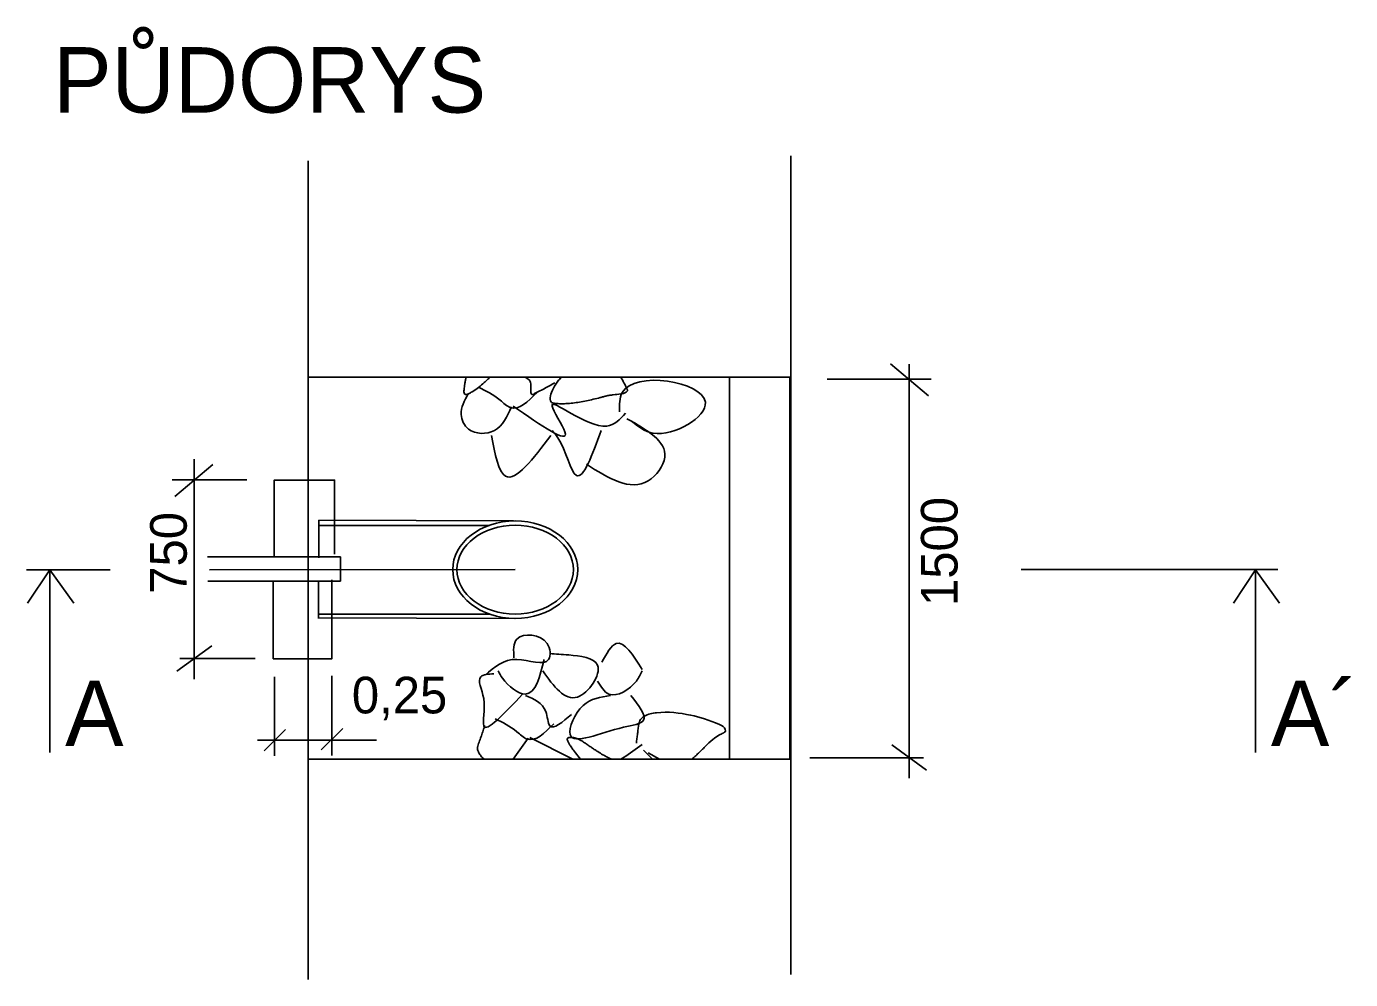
# Model space of a CAD drawing. Extents: x -463101.2 to -463058.2, y -1105044.4 to -1105011.4.
# Drawn here: x -463094.07 to -463083.23, y -1105030.57 to -1105022.77 of the extents above; entities that cross this region are included whole.
import ezdxf

# ---------------------------------------------------------------- set-up
doc = ezdxf.new("R2010")
doc.units = 0
doc.layers.add('Vrstva 14', color=7, linetype='Continuous')

msp = doc.modelspace()

# ---------------------------------------------------------------- linework, layer by layer
at = {"layer": 'Vrstva 14'}
for p, q in [((-463091.76794376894, -1105023.87000803), (-463091.76794376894, -1105030.5724223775)), ((-463087.8165389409, -1105023.8280037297), (-463087.8165389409, -1105030.5304180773)), ((-463086.99958763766, -1105025.531277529), (-463086.68764795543, -1105025.7934618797)), ((-463086.84766558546, -1105025.53473319), (-463086.84766558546, -1105028.9249225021)), ((-463088.31817793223, -1105025.6400270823), (-463091.7672940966, -1105025.6400270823)), ((-463087.8189958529, -1105025.6400270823), (-463088.31817793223, -1105025.6400270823)), ((-463088.31817793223, -1105025.6400270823), (-463088.31817793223, -1105028.7677961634)), ((-463087.82523562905, -1105028.7677961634), (-463087.82523562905, -1105025.6433654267)), ((-463087.51911575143, -1105025.6567217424), (-463086.6675204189, -1105025.6567217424)), ((-463092.54826919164, -1105026.3559565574), (-463092.86020887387, -1105026.6181409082)), ((-463092.70019124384, -1105026.3112801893), (-463092.70019124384, -1105028.1137976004)), ((-463092.27081989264, -1105026.4814007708), (-463092.8803364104, -1105026.4814007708)), ((-463091.68192638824, -1105027.1210487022), (-463091.68192638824, -1105026.811372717)), ((-463091.68192638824, -1105026.811372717), (-463090.08590284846, -1105026.8173622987)), ((-463091.6818170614, -1105026.854244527), (-463090.2832931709, -1105026.854244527)), ((-463091.5030528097, -1105027.112724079), (-463092.5921017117, -1105027.112724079)), ((-463091.5030528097, -1105027.310850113), (-463091.5030528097, -1105027.112724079)), ((-463094.07454247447, -1105027.218025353), (-463093.39045514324, -1105027.217837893)), ((-463093.88432615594, -1105027.2198520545), (-463093.6869389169, -1105027.4923547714)), ((-463092.57463033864, -1105027.2176143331), (-463090.07254473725, -1105027.2169286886)), ((-463085.93030603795, -1105027.2157935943), (-463083.82688213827, -1105027.2152171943)), ((-463084.0108773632, -1105027.2198520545), (-463083.81349012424, -1105027.4923547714)), ((-463092.58907011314, -1105027.310850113), (-463091.5030528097, -1105027.310850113)), ((-463091.6844222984, -1105027.3104338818), (-463091.6844222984, -1105027.6159563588)), ((-463091.68480347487, -1105027.612150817), (-463090.0753138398, -1105027.6165200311)), ((-463091.6844222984, -1105027.5801516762), (-463090.2864260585, -1105027.5801516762)), ((-463092.55799873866, -1105027.839473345), (-463092.8432007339, -1105028.0487452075)), ((-463092.2022732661, -1105027.945707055), (-463092.81898827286, -1105027.945707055)), ((-463092.0442134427, -1105028.0938394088), (-463092.0442134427, -1105028.7407540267)), ((-463091.5736301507, -1105028.0867051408), (-463091.5736301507, -1105028.7383759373)), ((-463092.129133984, -1105028.699839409), (-463091.953133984, -1105028.5258394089)), ((-463091.66055069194, -1105028.692705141), (-463091.48455069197, -1105028.5187051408)), ((-463092.18254953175, -1105028.6138394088), (-463091.2082134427, -1105028.6138394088)), ((-463089.9668118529, -1105028.597650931), (-463090.08959707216, -1105028.7677961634)), ((-463089.95281185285, -1105028.591650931), (-463089.60072510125, -1105028.7677961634)), ((-463086.98985809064, -1105028.6504018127), (-463086.7046560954, -1105028.8596736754)), ((-463088.31817793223, -1105028.7677961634), (-463091.7672940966, -1105028.7677961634)), ((-463089.0208118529, -1105028.695650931), (-463088.9487704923, -1105028.7677961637)), ((-463088.8898941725, -1105028.7677961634), (-463088.9828118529, -1105028.715650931)), ((-463088.31817793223, -1105028.7677961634), (-463087.82523562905, -1105028.7677961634)), ((-463087.66052840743, -1105028.756635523), (-463086.72886855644, -1105028.756635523))]:
    msp.add_line(p, q, dxfattribs=at)
for points in [[(-463092.0463878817, -1105027.1189083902), (-463092.0463878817, -1105026.4837396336), (-463091.55136565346, -1105026.4837396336), (-463091.55136565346, -1105027.0897722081)], [(-463093.88432615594, -1105028.714180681), (-463093.88432615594, -1105027.2198520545), (-463094.06566395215, -1105027.4923547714)], [(-463084.0108773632, -1105028.714180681), (-463084.0108773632, -1105027.2198520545), (-463084.1922151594, -1105027.4923547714)], [(-463091.57323458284, -1105027.3008608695), (-463091.57323458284, -1105027.9459002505), (-463092.0543510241, -1105027.9459002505), (-463092.0543510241, -1105027.3122774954)]]:
    msp.add_lwpolyline(points, dxfattribs=at)
for major_axis, ratio in [((0.5118952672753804, 0), 0.7792053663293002), ((0.47700487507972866, 0), 0.7630554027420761)]:
    msp.add_ellipse((-463090.07254473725, -1105027.2169286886), major_axis=major_axis, ratio=ratio, dxfattribs=at)
for points in [[(-463089.21736382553, -1105025.9239442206), (-463089.1973638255, -1105025.7679442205), (-463088.5153638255, -1105025.8459442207), (-463088.9433638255, -1105026.0999442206), (-463089.11936382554, -1105026.0019442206)], [(-463090.27786681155, -1105025.6400270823), (-463090.30171401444, -1105025.6625953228), (-463090.3255342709, -1105025.6844926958), (-463090.3730563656, -1105025.7248573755), (-463090.4203579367, -1105025.7582861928), (-463090.4439025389, -1105025.7715137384), (-463090.45564418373, -1105025.77710076), (-463090.46150682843, -1105025.7796182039), (-463090.464436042, -1105025.7808054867), (-463090.4659001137, -1105025.7813809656), (-463090.46663201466, -1105025.781664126), (-463090.46736382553, -1105025.7819442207), (-463090.4709831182, -1105025.783105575), (-463090.4742658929, -1105025.7837156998), (-463090.4798698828, -1105025.7833583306), (-463090.4875675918, -1105025.7768656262), (-463090.49160965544, -1105025.745028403), (-463090.4856333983, -1105025.6961698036), (-463090.48080820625, -1105025.6684003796), (-463090.4757822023, -1105025.6400270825)], [(-463089.8933638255, -1105025.7659442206), (-463090.1133638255, -1105025.8899442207), (-463090.19536382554, -1105025.8299442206), (-463090.3733638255, -1105025.7239442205)], [(-463089.7473638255, -1105025.6879442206), (-463089.8363742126, -1105025.7354741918), (-463089.8809168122, -1105025.75896262), (-463089.90315791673, -1105025.7705318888), (-463089.91426597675, -1105025.7762595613), (-463089.9253638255, -1105025.7819442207), (-463089.92854551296, -1105025.7832982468), (-463089.9313403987, -1105025.7839325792), (-463089.9358697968, -1105025.7831999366), (-463089.94138732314, -1105025.7748338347), (-463089.94385909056, -1105025.7393336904), (-463089.9455832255, -1105025.695638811), (-463089.95016621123, -1105025.6770292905), (-463089.9593638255, -1105025.6639442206), (-463089.9898438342, -1105025.6400270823)], [(-463089.2076965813, -1105025.6400270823), (-463089.15736382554, -1105025.7359442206), (-463089.155282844, -1105025.7406332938), (-463089.15411682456, -1105025.7449794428), (-463089.15435126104, -1105025.7527059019), (-463089.1638371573, -1105025.7647360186), (-463089.2088860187, -1105025.77862944), (-463089.2696737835, -1105025.785680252), (-463089.29883330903, -1105025.789157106), (-463089.3118556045, -1105025.7913239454), (-463089.3178212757, -1105025.7925695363), (-463089.3233638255, -1105025.7939442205), (-463089.35023387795, -1105025.8011824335), (-463089.37756314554, -1105025.8083756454), (-463089.43324913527, -1105025.8222669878), (-463089.5462796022, -1105025.845548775), (-463089.6568521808, -1105025.8580282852), (-463089.70946581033, -1105025.858416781), (-463089.73479804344, -1105025.856833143), (-463089.74718221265, -1105025.8555574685), (-463089.75329902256, -1105025.8547937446), (-463089.7593638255, -1105025.8539442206), (-463089.7650533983, -1105025.8526644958), (-463089.77002024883, -1105025.8506431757), (-463089.7778731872, -1105025.8445328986), (-463089.7858678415, -1105025.825141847), (-463089.7759068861, -1105025.7664781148), (-463089.7406686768, -1105025.6980681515), (-463089.71706676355, -1105025.6664943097), (-463089.70438193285, -1105025.6524652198), (-463089.6913409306, -1105025.6400270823)], [(-463090.10336382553, -1105025.8839442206), (-463090.2433638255, -1105026.0779442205), (-463090.4553638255, -1105026.0659442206), (-463090.5153638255, -1105025.9479442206), (-463090.4573638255, -1105025.7779442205)], [(-463090.0893638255, -1105025.8779442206), (-463089.6653638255, -1105026.0899442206), (-463089.77136382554, -1105025.8779442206), (-463089.3233638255, -1105026.0419442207), (-463089.1693638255, -1105025.9359442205)], [(-463089.15736382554, -1105025.9819442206), (-463088.84736382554, -1105026.2959442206), (-463088.98336382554, -1105026.4899442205), (-463089.48936382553, -1105026.3539442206)], [(-463089.7813638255, -1105026.1199442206), (-463090.1513638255, -1105026.4519442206), (-463090.2673638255, -1105026.1199442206)], [(-463089.36936382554, -1105026.0779442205), (-463089.5713638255, -1105026.4459442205), (-463089.7233638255, -1105026.1379442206), (-463089.77136382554, -1105026.0779442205)], [(-463090.3188118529, -1105028.081650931), (-463090.0588118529, -1105027.9516509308), (-463089.7988118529, -1105027.9516509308), (-463089.81081185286, -1105027.821650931), (-463090.0588118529, -1105027.7856509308), (-463090.08281185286, -1105027.939650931)], [(-463089.8468118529, -1105028.0456509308), (-463089.5628118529, -1105028.259650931), (-463089.3988118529, -1105027.999650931), (-463089.6348118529, -1105027.915650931), (-463089.78881185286, -1105027.9036509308)], [(-463089.3628118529, -1105027.975650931), (-463089.24481185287, -1105027.821650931), (-463089.03281185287, -1105028.033650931)], [(-463089.8348118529, -1105027.9516509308), (-463089.9888118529, -1105028.235650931), (-463090.1768118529, -1105028.105650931), (-463090.21281185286, -1105028.0456509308)], [(-463090.0128118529, -1105028.235650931), (-463090.3308118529, -1105028.4956509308), (-463090.3308118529, -1105028.2716509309), (-463090.35481185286, -1105028.0936509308), (-463090.2488118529, -1105028.0696509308)], [(-463089.3988118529, -1105028.1296509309), (-463089.30481185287, -1105028.235650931), (-463089.0808118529, -1105028.1296509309), (-463089.03281185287, -1105028.0456509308)], [(-463089.6108118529, -1105028.401650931), (-463089.78881185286, -1105028.4956509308), (-463089.8228118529, -1105028.377650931), (-463089.9888118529, -1105028.247650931)], [(-463089.12681185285, -1105028.247650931), (-463089.0208118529, -1105028.449650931), (-463089.1868118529, -1105028.507650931), (-463089.6228118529, -1105028.567650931), (-463089.51681185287, -1105028.3296509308), (-463089.2928118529, -1105028.247650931)], [(-463089.75681185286, -1105028.479650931), (-463089.9768118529, -1105028.6036509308), (-463090.0588118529, -1105028.543650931), (-463090.2368118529, -1105028.4376509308)], [(-463089.0808118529, -1105028.6376509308), (-463089.07612817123, -1105028.5985859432), (-463089.0711693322, -1105028.5595375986), (-463089.0660317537, -1105028.5205459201), (-463089.06081185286, -1105028.4816509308), (-463089.0587982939, -1105028.4713895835), (-463089.055638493, -1105028.4617825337), (-463089.04604891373, -1105028.444475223), (-463089.01497109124, -1105028.417095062), (-463088.9146707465, -1105028.3881309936), (-463088.63709090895, -1105028.4082551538), (-463088.4008715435, -1105028.4845772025), (-463088.3522717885, -1105028.525860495), (-463088.35479934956, -1105028.5441411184), (-463088.3639512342, -1105028.5522984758), (-463088.3706468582, -1105028.5560823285), (-463088.3745430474, -1105028.557894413), (-463088.3766305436, -1105028.5587797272), (-463088.3788118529, -1105028.5596509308), (-463088.3939104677, -1105028.5663661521), (-463088.43953398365, -1105028.59561761), (-463088.50104796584, -1105028.6495341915), (-463088.5632133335, -1105028.710545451), (-463088.5944963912, -1105028.7403193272), (-463088.6258896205, -1105028.7677961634)], [(-463090.3301546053, -1105028.7677961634), (-463090.3418767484, -1105028.7551235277), (-463090.3528889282, -1105028.7422918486), (-463090.37098047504, -1105028.7161291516), (-463090.3808233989, -1105028.6892636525), (-463090.38152480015, -1105028.6755534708), (-463090.38062329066, -1105028.6686265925), (-463090.3788118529, -1105028.661650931), (-463090.364582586, -1105028.619183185), (-463090.3499043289, -1105028.5767270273), (-463090.3351798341, -1105028.5342328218), (-463090.3208118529, -1105028.4916509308)], [(-463089.53892956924, -1105028.7677961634), (-463089.5793885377, -1105028.7161609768), (-463089.58989791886, -1105028.7024076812), (-463089.6001824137, -1105028.6884992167), (-463089.6103431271, -1105028.674472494), (-463089.6204811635, -1105028.6603644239), (-463089.6276154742, -1105028.649417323), (-463089.63388765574, -1105028.637961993), (-463089.6395284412, -1105028.6261786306), (-463089.6447685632, -1105028.6142474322), (-463089.64590712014, -1105028.6106162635), (-463089.6463542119, -1105028.6067682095), (-463089.6461065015, -1105028.602883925), (-463089.64516065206, -1105028.5991440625), (-463089.64146510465, -1105028.5943380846), (-463089.6348118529, -1105028.591650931), (-463089.60948603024, -1105028.590371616), (-463089.5830696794, -1105028.59523248), (-463089.5685623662, -1105028.600179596), (-463089.55448984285, -1105028.6057345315), (-463089.5408384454, -1105028.6120876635), (-463089.5275945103, -1105028.6194293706), (-463089.4977896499, -1105028.6385279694), (-463089.46876499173, -1105028.6585002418), (-463089.4398759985, -1105028.678606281), (-463089.410478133, -1105028.6981061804), (-463089.3963422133, -1105028.7070639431), (-463089.35412745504, -1105028.7329262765), (-463089.32486935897, -1105028.7491927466), (-463089.29352861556, -1105028.7645553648), (-463089.2854597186, -1105028.7677961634)], [(-463089.2119812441, -1105028.768393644), (-463089.20545194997, -1105028.7659735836), (-463089.1992477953, -1105028.7630425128), (-463089.1868118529, -1105028.7556509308), (-463089.03281185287, -1105028.649650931)]]:
    msp.add_spline(points, degree=3, dxfattribs=at)

# ---------------------------------------------------------------- texts
for s, height, p in [('PŮDORYS', 0.536004, (-463093.8558598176, -1105023.4756683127)), ('0,25', 0.3, (-463091.41011708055, -1105028.3938394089)), ('A´', 0.536004, (-463083.88449074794, -1105028.6605798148)), ('A', 0.536004, (-463093.7579395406, -1105028.6605798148))]:
    msp.add_text(s, height=height, dxfattribs=at).set_placement(p)
for s, p in [('1500', (-463086.4504348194, -1105027.5143400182)), ('750', (-463092.76214034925, -1105027.4143380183))]:
    msp.add_text(s, height=0.3, rotation=90, dxfattribs=at).set_placement(p)

doc.saveas('drawing.dxf')
